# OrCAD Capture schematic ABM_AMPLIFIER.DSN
size A
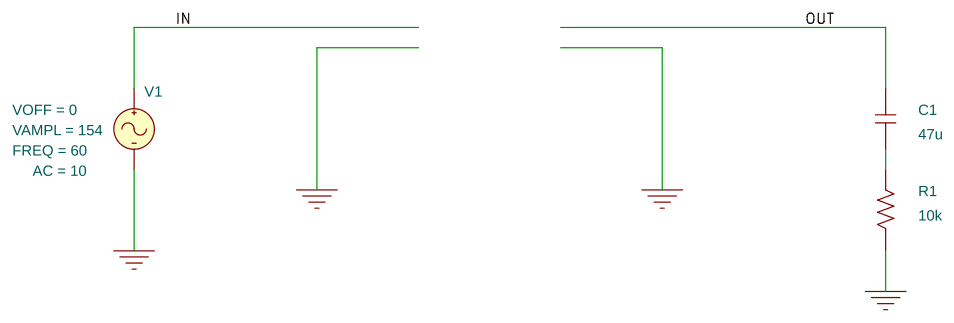
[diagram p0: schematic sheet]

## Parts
C1  47u  [cap196]
R1  10k  [AXRC05]
V1  VSIN

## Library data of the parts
C1 = C
R1 = R
V1 = VSIN: AC: 10; AppProp: Sine$Voltage$0$-1; DC: 0; FREQ: 60; VAMPL: 154; VOFF: 0

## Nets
0: R1.1 V1.2(-)
IN: V1.1(+)
OUT: C1.2
N00461: C1.1 R1.2
